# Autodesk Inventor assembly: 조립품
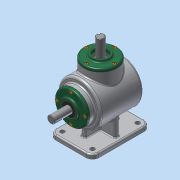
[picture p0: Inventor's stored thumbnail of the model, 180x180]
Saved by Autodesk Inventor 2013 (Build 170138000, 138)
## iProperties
Created: 2016-09
Part Number: 조립품
Document SubType Name: Assembly
Designer: Administrator
Author: Administrator
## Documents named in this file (14)
- C:\Users\Administrator\Desktop\460908V1009\조립품.iam
- C:\Users\Administrator\Desktop\460908V1009\본체.ipt
- C:\Users\Administrator\Desktop\460908V1009\커버.ipt
- C:\Users\Administrator\Desktop\460908V1009\M4.ipt
- C:\Users\Administrator\Desktop\460908V1009\베어링 6203.ipt
- C:\Users\Administrator\Desktop\460908V1009\메인 축.ipt
- 메인 축.ipt
- C:\Users\Administrator\Desktop\460908V1009\서브 축.ipt
- 서브 축.ipt
- C:\Users\Administrator\Desktop\460908V1009\오일실 17 32 8.ipt
- C:\Users\Administrator\Desktop\460908V1009\키 5x5.ipt
- C:\Users\Administrator\Desktop\460908V1009\키 4x4.ipt
- C:\Users\Administrator\Desktop\460908V1009\서브 베벨기어.ipt
- C:\Users\Administrator\Desktop\460908V1009\메인 베벨기어.ipt
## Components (8 placed, 1 different names)
1. M4:1
2. M4:3
3. M4:4
4. M4:5
5. M4:2
6. M4:6
7. M4:7
8. M4:8
